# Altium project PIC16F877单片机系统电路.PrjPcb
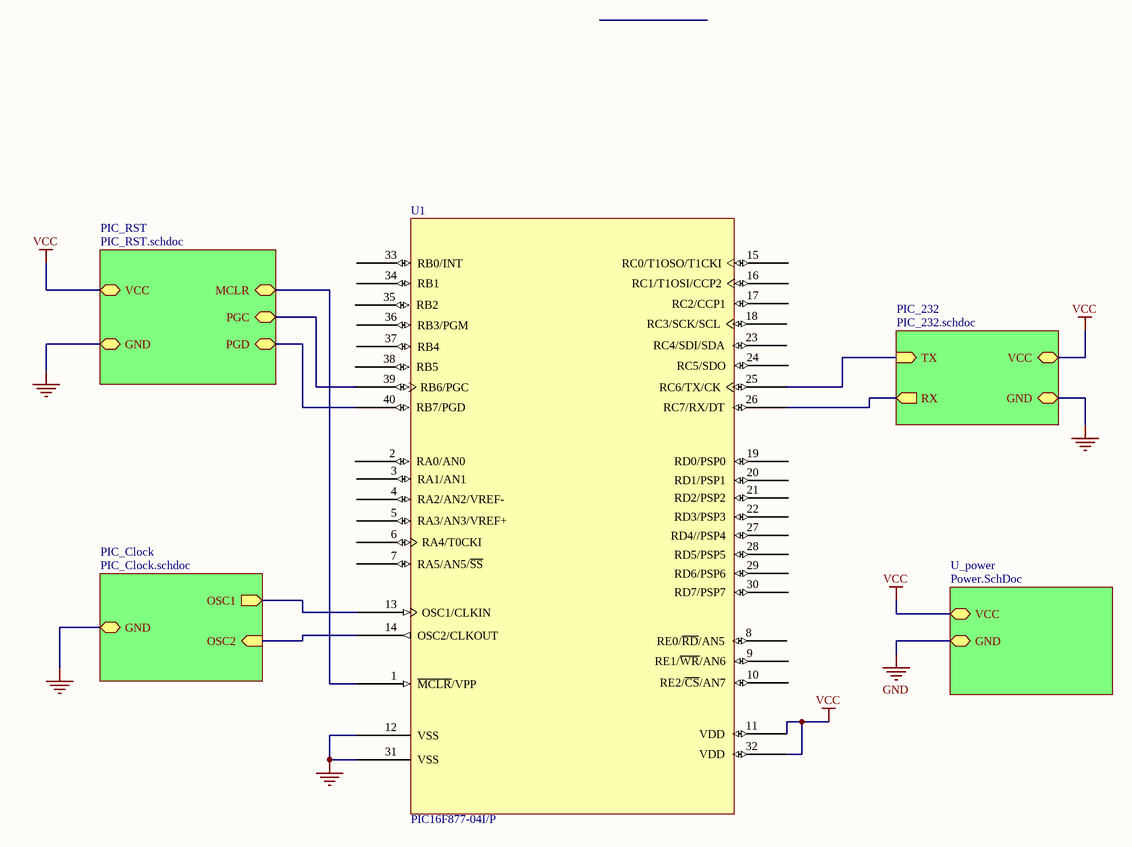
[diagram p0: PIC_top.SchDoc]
4 sheets, 1 parts. Net scope: hierarchical (ports join the sheet entries above them; power ports are global).
Sheets:
  PIC_top.SchDoc
    PIC_Clock = PIC_Clock.SchDoc
    PIC_232 = PIC_232.SchDoc
    U_power = Power.SchDoc

## Sheet PIC_top.SchDoc
size A4

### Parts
U1  PIC16F877-04I/P

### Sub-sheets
PIC_232 = PIC_232.schdoc: VCC, GND, TX (in), RX (out)
PIC_Clock = PIC_Clock.schdoc: OSC1 (out), OSC2 (in), GND
PIC_RST = PIC_RST.schdoc (file not in this document): GND, VCC, MCLR, PGC, PGD
U_power = Power.SchDoc: VCC, GND

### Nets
GND: U1.12(VSS) U1.31(VSS) ; sheet PIC_Clock/GND, sheet PIC_RST/GND, sheet PIC_232/GND, sheet U_power/GND
VCC: U1.11(VDD) U1.32(VDD) ; sheet PIC_RST/VCC, sheet PIC_232/VCC, sheet U_power/VCC
NetU1_1: U1.1(~{MCLR}/VPP) ; sheet PIC_RST/MCLR
NetU1_13: U1.13(OSC1/CLKIN) ; sheet PIC_Clock/OSC1
NetU1_14: U1.14(OSC2/CLKOUT) ; sheet PIC_Clock/OSC2
NetU1_25: U1.25(RC6/TX/CK) ; sheet PIC_232/TX
NetU1_26: U1.26(RC7/RX/DT) ; sheet PIC_232/RX
NetU1_39: U1.39(RB6/PGC) ; sheet PIC_RST/PGC
NetU1_40: U1.40(RB7/PGD) ; sheet PIC_RST/PGD

Not connected (* = marked no-connect by the designer): U1 2(RA0/AN0) 3(RA1/AN1) 4(RA2/AN2/VREF-) 5(RA3/AN3/VREF+) 6(RA4/T0CKI) 7(RA5/AN5/~{SS}) 8(RE0/~{RD}/AN5) 9(RE1/~{WR}/AN6) 10(RE2/~{CS}/AN7) 15(RC0/T1OSO/T1CKI) 16(RC1/T1OSI/CCP2) 17(RC2/CCP1) 18(RC3/SCK/SCL) 19(RD0/PSP0) 20(RD1/PSP1) 21(RD2/PSP2) 22(RD3/PSP3) 23(RC4/SDI/SDA) 24(RC5/SDO) 27(RD4//PSP4) 28(RD5/PSP5) 29(RD6/PSP6) 30(RD7/PSP7) 33(RB0/INT) 34(RB1) 35(RB2) 36(RB3/PGM) 37(RB4) 38(RB5)

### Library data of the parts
U1 = PIC16F877-04I/P: MCU

## Sheet PIC_Clock.SchDoc
size A4
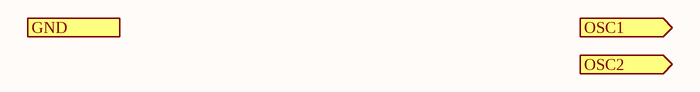
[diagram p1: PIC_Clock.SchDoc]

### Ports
GND, OSC1 (out), OSC2 (in)

## Sheet PIC_232.SchDoc
size A4
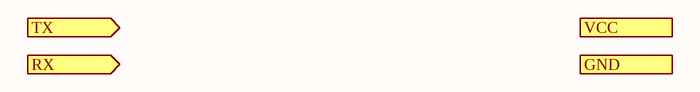
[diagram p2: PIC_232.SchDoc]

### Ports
GND, RX (out), TX (in), VCC

## Sheet Power.SchDoc
size A4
